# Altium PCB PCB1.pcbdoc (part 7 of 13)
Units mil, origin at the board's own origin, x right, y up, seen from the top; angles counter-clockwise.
Board outline 5895.51 x 5895.51 mil, 8 copper layers (Top Layer, L2_GND1, L3_SIG1, L4_GND2, L5_PWR, L6_SIG2, L7_GND3, Bottom Layer), stack 63.761 mil thick; 673 components, 558 nets, 2797 pads, 1861 vias.
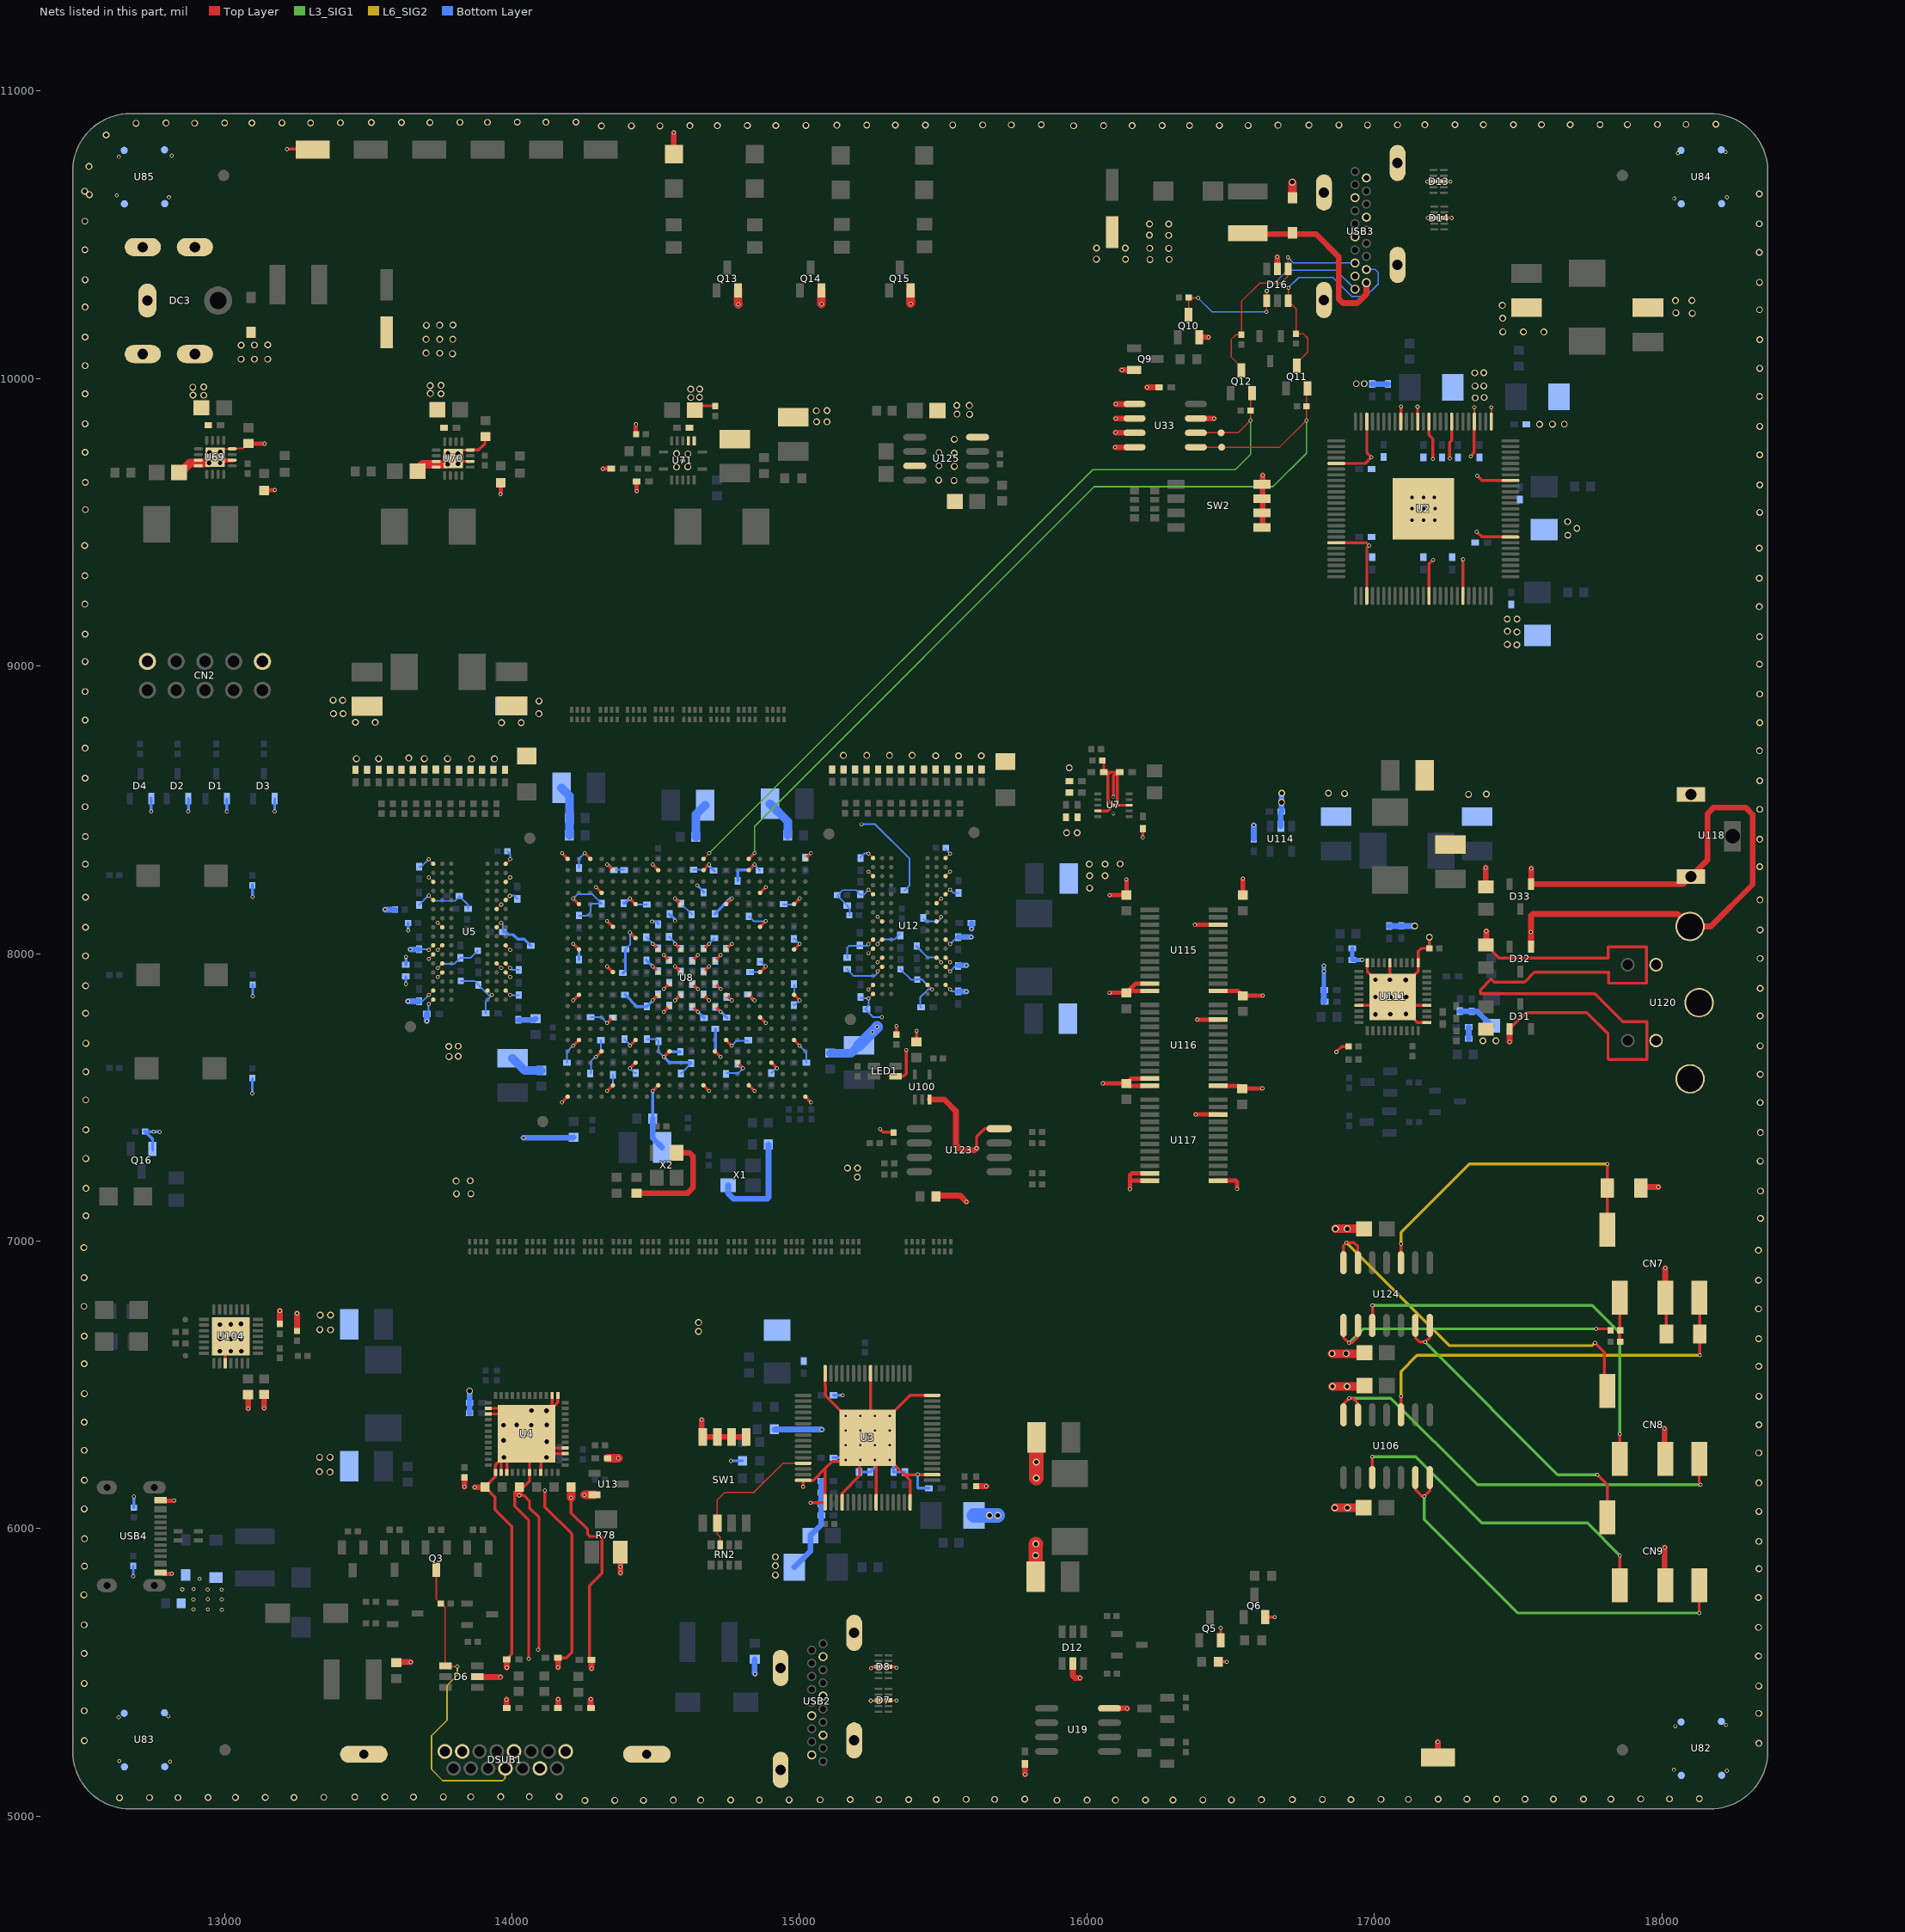
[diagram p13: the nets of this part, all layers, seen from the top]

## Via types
v1: diameter 23.62, hole 15.75, Top Layer to Bottom Layer, 621 vias
v2: diameter 13.8, hole 7.9, Top Layer to Bottom Layer, 567 vias
v3: diameter 13.78, hole 7.87, Top Layer to Bottom Layer, 529 vias
v4: diameter 13.78, hole 7.9, Top Layer to Bottom Layer, 114 vias
v5: diameter 15.75, hole 7.87, Top Layer to Bottom Layer, 16 vias
v6: diameter 24, hole 12, Top Layer to Bottom Layer, 10 vias
v7: diameter 11.81, hole 7.87, Top Layer to Bottom Layer, 4 vias

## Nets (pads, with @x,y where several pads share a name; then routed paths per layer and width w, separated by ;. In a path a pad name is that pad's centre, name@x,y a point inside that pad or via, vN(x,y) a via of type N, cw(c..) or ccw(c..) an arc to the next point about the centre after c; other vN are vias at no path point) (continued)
GND: C1.1 C2.1 C3.1 C4.1 C5.1 C6.1 C7.1 C8.1 C9.1 C10.1 C11.1 C12.1 C13.1 C14.1 C15.1 C16.1 C17.1 C18.1 C19.1 C20.1 C21.1 C22.1 C23.1 C24.1 C25.1 C29.1 C30.1 C31.1 C32.1 C33.1 C34.1 C35.1 C36.1 C37.1 C38.1 C39.1 C40.1 C41.1 C42.1 C43.1 C44.1 C45.1 C46.1 C47.1 C48.1 C49.1 C50.1 C51.1 C52.1 C53.1 C54.1 C55.1 C56.1 C57.1 C58.1 C59.1 C60.1 C61.1 C62.1 C63.1 C64.1 C65.1 C66.1 C67.1 C68.1 C69.1 C70.1 C71.1 C72.1 C73.1 C74.1 C75.1 C76.1 C77.1 C78.1 C79.1 C80.1 C81.1 C82.1 C83.1 C84.1 C85.1 C86.1 C87.1 C88.1 C89.1 C90.1 C91.1 C92.1 C93.1 C94.1 C95.1 C96.1 C97.1 C98.1 C99.1 C100.1 C101.1 C102.2 C103.2 C104.2 C105.2 C106.2 C107.1 C108.2 C109.1 C111.1 C112.1 C113.1 C114.1 C115.1 C116.1 C117.1 C118.1 C119.2 C120.1 C121.1 C122.1 C123.1 C124.2 C125.1 C128.1 C129.2 C132.2 C133.2 C135.2 C136.2 C141.1 C142.1 C143.1 C144.1 C145.1 C146.1 C147.1 C148.1 C149.1 C150.1 C153.2 C157.2 C158.2 C159.2 C162.2 C166.1 C167.1 C169.1 C171.1 C173.2 C176.1 C178.2 C179.2 C180.2 C181.2 C182.2 C183.2 C184.2 C185.1 C186.1 C187.1 C188.1 C189.1 C190.1 C191.1 C192.2 C193.1 C194.1 C195.1 C196.1 C197.1 C198.1 C199.1 C200.1 C201.1 C204.1 C205.1 C206.1 C207.1 C208.1 C209.1 C210.1 C211.1 C212.1 C213.1 C214.1 C215.1 C216.1 C217.2 C218.2 C219.2 C220.1 C221.1 C222.1 C223.1 C224.1 C225.1 C226.1 C227.1 C228.1 C229.1 C230.1 C231.1 C232.1 C233.1 C234.1 C235.1 C236.1 C237.1 C238.1 C239.1 C240.1 C241.1 C242.1 C243.1 C244.1 C245.1 C246.1 C247.1 C248.1 C249.1 C250.1 C251.1 C259.2 C260.2 C261.1 C262.1 C263.1 C264.1 C265.1 C266.1 C267.1 C268.1 C269.1 C270.1 C271.1 C272.1 C273.1 C274.1 C275.1 C276.1 C277.1 C278.1 C279.1 C280.1 C281.1 C282.1 C283.1 C284.1 C285.1 C286.1 C287.1 C288.1 C289.1 C290.1 C291.1 C292.1 C293.1 C294.1 C295.1 C296.1 C297.1 C298.1 C299.1 C300.1 C301.1 C302.1 C303.1 C304.1 C305.1 C306.1 C307.1 C308.1 C309.1 C310.1 C311.1 C312.1 C313.1 C314.1 C315.1 C319.2 C322.2 C328.1 C329.1 C330.1 C331.2 C332.1 C333.2 C334.1 C335.2 C336.1 C337.1 C338.1 C339.2 C340.1 C343.1 C344.1 C345.2 C346.2 C347.2 C348.2 C349.2 C350.2 C351.1 C352.1 C354.1 C355.1 C356.1 C357.1 CN2.2 CN2.10 CN7.3 CN8.3 CN9.3 D1.1 D2.1 D3.1 D4.1 D6.2 D7.3 D7.8 D8.3 D8.8 D12.2 D13.3 D13.8 D14.3 D14.8 D16.2 D20.2 D21.2 D26.2 D30.2 D31.1 D32.1 D33.1 DC3.4 DC3.6 DSUB1.5 DSUB1.6 DSUB1.7 DSUB1.8 DSUB1.10 DSUB1.16 DSUB1.17 L36.2 LED1.2 Q5.2 Q6.2 Q9.2 Q10.2 Q13.2 Q14.2 Q15.2 Q16.2 R1.2 R2.2 R25.1 R26.2 R51.2 R52.2 R53.2 R78.3 R84.1 R85.1 R86.1 R97.1 R103.1 R120.2 R121.2 R134.1 R137.1 R139.1 R141.1 R149.1 R158.1 R170.2 R172.2 R174.2 R175.1 R176.1 R185.1 R186.2 R187.2 R188.2 R189.2 R193.2 R194.1 R196.1 R197.1 R198.1 SW1.5 SW1.6 SW1.7 SW1.8 SW2.5 SW2.6 SW2.7 SW2.8 U2.5 U2.19 U2.28 U2.39 U2.45 U2.58 U2.68 U2.76 U2.79 U2.83 U2.87 U2.89 U2.92 U2.98 U2.101 U3.16 U3.17 U3.20 U3.26 U3.32 U3.34 U3.48 U3.56 U3.64 U3.65 U4.1 U4.2 U4.14 U4.15 U4.25 U4.26 U4.27 U4.31 U4.33 U4.39 U4.40 U4.49 U5.A9 U5.B1 U5.B3 U5.B9 U5.D1 U5.D8 U5.E1 U5.E2 U5.E8 U5.F9 U5.G1 U5.G8 U5.G9 U5.J2 U5.J8 U5.L2 U5.M1 U5.M9 U5.P1 U5.P9 U5.T1 U5.T9 U7.4 U7.8 U7.11 U8.A1 U8.A3 U8.A22 U8.AA5 U8.AA9 U8.AA13 U8.AA17 U8.AB1 U8.AB22 U8.B5 U8.B9 U8.B13 U8.B17 U8.D4 U8.D18 U8.E2 U8.E7 U8.E11 U8.E15 U8.E21 U8.G5 U8.G18 U8.H7 U8.J2 U8.J9 U8.J11 U8.J13 U8.J15 U8.J21 U8.K10 U8.K12 U8.K14 U8.L5 U8.L9 U8.L11 U8.L13 U8.L18 U8.M10 U8.M12 U8.M14 U8.N2 U8.N9 U8.N11 U8.N13 U8.N15 U8.N17 U8.N21 U8.P10 U8.P12 U8.P14 U8.R5 U8.R18 U8.U2 U8.U7 U8.U15 U8.U21 U8.V4 U8.V10 U8.V14 U8.W7 U8.W16 U8.W19 U12.A9 U12.B1 U12.B3 U12.B9 U12.D1 U12.D8 U12.E1 U12.E2 U12.E8 U12.F9 U12.G1 U12.G8 U12.G9 U12.J2 U12.J8 U12.L2 U12.M1 U12.M9 U12.P1 U12.P9 U12.T1 U12.T9 U13.2 U14.1 U19.4 U25.1 U33.1 U33.2 U33.3 U33.4 U33.7 U69.6 U69.8 U69.15 U69.16 U69.17 U70.6 U70.8 U70.15 U70.16 U70.17 U71.2 U71.3 U71.15 U75.1 U76.1 U77.1 U82.1 U82.2 U82.3 U82.4 U83.1 U83.2 U83.3 U83.4 U84.1 U84.2 U84.3 U84.4 U85.1 U85.2 U85.3 U85.4 U100.3 U102.1 U104.3 U104.29 U105.2 U111.7 U111.21 U111.24 U111.31 U111.36 U111.40 U111.41 U114.2 U115.11 U115.12 U115.13 U115.22 U116.11 U116.12 U116.13 U116.22 U117.11 U117.12 U117.13 U117.22 U118.2 U118.3 U120.1 U120.2 U120.5 U120.6 U120.7 U122.1 U123.4 U125.3 U125.8 USB2.2 USB2.5 USB2.8 USB2.11 USB2.17 USB2.20 USB3.2 USB3.5 USB3.8 USB3.11 USB3.17 USB3.20 USB4.1 USB4.12 X1.2 X2.2 | length 35669.5
  Top Layer w4.7: v2(13710.63,7824.03) U5.A9@13726.38,7839.78 ; v2(13710.63,7855.53) U5.B9@13726.38,7871.28 ; v2(13710.63,7981.52) U5.F9@13726.38,7997.26 ; v2(13710.63,8013.02) U5.G9@13726.38,8028.76 ; v2(13710.63,8201.99) U5.M9@13726.38,8186.24 ; v2(13710.63,8264.98) U5.P9@13726.38,8249.23 ; v2(13710.63,8327.97) U5.T9@13726.38,8312.22 ; v2(13742.12,7918.52) U5.D8@13757.87,7934.27 ; v2(13742.12,7950.02) U5.E8@13757.87,7965.76 ; v2(13742.12,8013.02) U5.G8@13757.87,8028.76 ; v2(13742.12,8107.49) U5.J8@13757.87,8091.75 ; U5.B3@13915.35,7871.28 v2(13931.09,7855.53) ; U5.E2@13946.85,7965.76 v2(13962.59,7950.02) ; U5.J2@13946.85,8091.75 v2(13962.59,8107.49) ; U5.L2@13946.85,8154.74 v2(13962.59,8170.48) ; U5.B1@13978.34,7871.28 v2(13994.08,7855.53) ; U5.D1@13978.34,7934.27 v2(13994.08,7918.52) ; U5.E1@13978.34,7965.76 v2(13994.08,7950.02) ; U5.G1@13978.34,8028.76 v2(13994.08,8013.02) ; U5.M1@13978.34,8186.24 13978.34,8186.46 v2(13992.51,8200.62) ; U5.P1@13978.34,8249.23 v2(13994.08,8264.98) ; U5.T1@13978.34,8312.22 v2(13994.08,8327.97) ; v2(15240.63,7844.03) U12.A9@15256.38,7859.78 ; v2(15240.63,7875.53) U12.B9@15256.38,7891.28 ; v2(15240.63,8001.52) U12.F9@15256.38,8017.26 ; v2(15240.63,8033.02) U12.G9@15256.38,8048.76 ; v2(15240.63,8221.99) U12.M9@15256.38,8206.24 ; v2(15240.63,8284.98) U12.P9@15256.38,8269.23 ; v2(15240.63,8347.97) U12.T9@15256.38,8332.22 ; v3(15248.36,5402) 15273.76,5402 D7.8@15274.92,5403.16 ; v2(15272.12,7938.52) U12.D8@15287.87,7954.27 ; v2(15272.12,7970.02) U12.E8@15287.87,7985.76 ; v2(15272.12,8033.02) U12.G8@15287.87,8048.76 ; v2(15272.12,8127.49) U12.J8@15287.87,8111.75 ; D7.3@15309.58,5403.16 v3(15337.36,5403.16) ; U12.B3@15445.35,7891.28 v2(15461.09,7875.53) ; U12.E2@15476.85,7985.76 v2(15492.59,7970.02) ; U12.J2@15476.85,8111.75 v2(15492.59,8127.49) ; U12.L2@15476.85,8174.74 v2(15492.59,8190.48) ; U12.B1@15508.34,7891.28 v2(15524.08,7875.53) ; U12.D1@15508.34,7954.27 v2(15524.08,7938.52) ; U12.E1@15508.34,7985.76 v2(15524.08,7970.02) ; U12.G1@15508.34,8048.76 v2(15524.08,8033.02) ; U12.M1@15508.34,8206.24 v2(15524.08,8221.99) ; U12.P1@15508.34,8269.23 v2(15524.08,8284.98) ; U12.T1@15508.34,8332.22 v2(15524.08,8347.97)
  Top Layer w5: U69.17@12979.36,9752.17 12982.08,9754.89 U69.8@13027.74,9754.89 ; U69.8@13029.69,9757.02 13066.99,9757.02 C195.1@13085.26,9775.29
  Top Layer w6.2: U2.79@17347.52,9850.15 v3(17347.52,9900) ; v3(17406.36,9900) 17406.58,9899.78 U2.76@17406.58,9850.15
  Top Layer w10: U104.3@13003.01,6575.31 13003.01,6649.23 U104.29@13022.69,6668.91 ; v3(13217.85,10797.25) 13218.27,10797.67 U75.1@13307.73,10797.67 ; U70.17@13791.43,9711.95 13854.5,9711.95 U70.6@13855.13,9711.32 ; U70.17@13807.82,9730.95 13827.83,9750.97 U70.8@13855.03,9750.97 ; U70.8@13859.91,9751.64 13884.78,9751.64 13905.96,9772.82 13905.96,9800.41 C198.1@13908.29,9802.74 ; U4.15@13917.5,6398.9 U4.49@13982.46,6398.9 ; U4.14@13917.5,6418.58 13962.78,6418.58 U4.49@13982.46,6398.9 ; U4.26@13962.78,6196.14 U4.49@13962.78,6241.42 ; C114.1@13981.9,5546 13999.36,5563.46 13999.36,6008 13941.36,6066 13941.36,6110.34 13907.69,6144.01 R84.1@13906.7,6145 13943.09,6181.39 U4.25@13943.09,6196.14 13943.09,6221.73 U4.49@13962.78,6241.42 ; U4.27@13982.46,6196.14 U4.49@13982.46,6261.1 ; v4(14025.49,6116.04) 14042.32,6116.04 14061.36,6097 14061.36,6072 14094.36,6039 14094.36,5582 v3(14091.36,5579) ; R85.1@14025.49,6143.79 14009.36,6127.66 14009.36,6079 14058.36,6030 v4(14058.36,5548) ; R85.1@14026.7,6145 14041.36,6145 14061.2,6164.84 U4.31@14061.2,6196.14 U4.49@14061.2,6320.16 ; U4.33@14100.57,6196.14 U4.49@14100.57,6280.79 ; v3(14114.36,6133) 14114.36,6076 14208.36,5982 14208.36,5570 14189.36,5551 C113.1@14159.82,5551 ; U4.2@14139.94,6463.86 U4.49@14139.94,6418.58 ; U4.1@14159.63,6463.86 14159.63,6438.27 U4.49@14139.94,6418.58 ; v2(14174.29,7482.92) U8.AB1@14193.96,7502.6 ; v2(14174.29,8349.07) U8.A1@14193.96,8329.4 ; U4.39@14185.22,6261.1 14120.26,6261.1 U4.49@14100.57,6280.79 ; U4.40@14185.22,6280.79 U4.49@14100.57,6280.79 ; v3(14206.02,6108) 14206.02,6054.34 14263.36,5997 14263.36,5981 14271.36,5973 14313.36,5973 14313.36,5845 14270.36,5802 14270.36,5550.46 C112.1@14277.13,5543.68 ; v2(14213.67,7679.79) U8.U2@14233.34,7699.47 ; v2(14213.67,7837.27) U8.N2@14233.34,7856.94 ; v2(14213.67,8034.1) U8.J2@14233.34,8014.43 ; v2(14213.67,8191.57) U8.E2@14233.34,8171.9 ; v2(14253.04,8349.07) U8.A3@14272.71,8329.4 ; v2(14292.41,7640.42) U8.V4@14312.08,7660.1 ; v2(14292.41,8230.95) U8.D4@14312.08,8211.27 ; v2(14331.79,7522.32) U8.AA5@14351.46,7542 ; v2(14331.79,7758.52) U8.R5@14351.46,7778.2 ; v2(14331.79,7955.37) U8.L5@14351.46,7935.7 ; v2(14331.79,8112.84) U8.G5@14351.46,8093.16 ; v2(14331.79,8309.69) U8.B5@14351.46,8290.01 ; v2(14410.52,7601.05) U8.W7@14430.19,7620.73 ; v2(14410.52,7679.79) U8.U7@14430.19,7699.47 ; v2(14410.52,8073.47) U8.H7@14430.19,8053.8 ; v2(14410.52,8191.57) U8.E7@14430.19,8171.9 ; v2(14489.26,7522.32) U8.AA9@14508.93,7542 ; v2(14489.26,7837.27) U8.N9@14508.93,7856.94 ; v2(14489.26,7955.37) U8.L9@14508.93,7935.7 ; v2(14489.26,8034.1) U8.J9@14508.93,8014.43 ; v2(14489.26,8309.69) U8.B9@14508.93,8290.01 ; v2(14528.63,7640.42) U8.V10@14548.3,7660.1 ; v2(14528.63,7797.9) U8.P10@14548.3,7817.57 ; v2(14528.63,7876.62) U8.M10@14548.3,7896.3 ; v2(14528.63,7994.73) U8.K10@14548.3,7975.06 ; v2(14567.99,7837.27) U8.N11@14587.66,7856.94 ; v2(14567.99,7955.37) U8.L11@14587.66,7935.7 ; v2(14567.99,8034.1) U8.J11@14587.66,8014.43 ; v2(14567.99,8191.57) U8.E11@14587.66,8171.9 ; U8.P12@14627.06,7817.57 v2(14646.74,7797.9) ; U8.M12@14627.06,7896.3 v2(14646.74,7876.62) ; U8.K12@14627.06,7975.06 v2(14646.74,7994.73) ; C199.1@14651.76,9901.92 14654.81,9904.97 R139.1@14703.55,9904.97 ; U8.AA13@14666.41,7542 v2(14686.09,7522.32) ; U8.N13@14666.41,7856.94 v2(14686.09,7837.27) ; U8.L13@14666.41,7935.7 v2(14686.09,7955.37) ; U8.J13@14666.41,8014.43 v2(14686.09,8034.1) ; U8.B13@14666.41,8290.01 v2(14686.09,8309.69) ; U8.V14@14705.78,7660.1 v2(14725.46,7640.42) ; U8.P14@14705.78,7817.57 v2(14725.46,7797.9) ; U8.M14@14705.78,7896.3 v2(14725.46,7876.62) ; U8.K14@14705.78,7975.06 v2(14725.46,7994.73) ; U8.U15@14745.16,7699.47 v2(14764.84,7679.79) ; U8.N15@14745.16,7856.94 v2(14764.84,7837.27) ; U8.J15@14745.16,8014.43 v2(14764.84,8034.1) ; U8.E15@14745.16,8171.9 v2(14764.84,8191.57) ; U8.W16@14784.52,7620.73 v2(14804.2,7601.05) ; U8.AA17@14823.89,7542 v2(14843.57,7522.32) ; U8.N17@14823.89,7856.94 v2(14843.57,7837.27) ; U8.B17@14823.89,8290.01 v2(14843.57,8309.69) ; U8.R18@14863.26,7778.2 v2(14882.94,7758.52) ; U8.L18@14863.26,7935.7 v2(14882.94,7955.37) ; U8.G18@14863.26,8093.16 v2(14882.94,8112.84) ; U8.D18@14863.26,8211.27 v2(14882.94,8230.95) ; U8.W19@14902.63,7620.73 v2(14922.31,7601.05) ; U8.U21@14981.36,7699.47 v2(15001.04,7679.79) ; U8.N21@14981.36,7856.94 v2(15001.04,7837.27) ; U8.J21@14981.36,8014.43 v2(15001.04,8034.1) ; U8.E21@14981.36,8171.9 v2(15001.04,8191.57) ; v3(15012.95,6146) U3.16@15012.95,6168.36 15048.72,6168.36 15089.72,6209.36 ; U8.AB22@15020.76,7502.6 v2(15040.44,7482.92) ; U8.A22@15020.76,8329.4 v2(15040.44,8349.07) ; v3(15038.36,6090) 15088.13,6090 U3.17@15089.72,6091.59 15089.72,6209.36 ; U3.64@15089.72,6540.41 15089.72,6499.64 15090.36,6499 15090.36,6463 v5(15160.59,6392.77) v5(15211.77,6341.59) U3.65@15237.36,6316 ; U3.20@15148.78,6091.59 15148.78,6123.42 15209.36,6184 U3.65@15209.36,6288 ; U3.56@15247.2,6540.41 15247.2,6325.84 U3.65@15237.36,6316 ; v3(15249.36,5515) 15254.35,5519.99 D8.8@15274.77,5519.99 D8.3@15309.43,5519.99 15333.37,5519.99 v3(15337.36,5516) ; U3.26@15266.89,6091.59 U3.65@15266.89,6286.47 ; D7.8@15274.92,5403.16 D7.3@15309.58,5403.16 ; v3(15280.67,7389.79) 15291.71,7378.76 R25.1@15327.06,7378.76 ; v5(15314.13,6392.77) 15385,6463.64 U3.48@15461.77,6463.64 ; LED1.2@15334.76,7573.28 15361.64,7573.28 15371.36,7583 v3(15371.36,7665) ; R185.1@15337.36,7718.04 v3(15337.36,7748) ; U3.32@15385,6091.59 15385,6168.36 15365.31,6188.05 ; C1.1@15407.36,7693.56 v3(15407.36,7732) ; v3(15411.36,6189) 15410.98,6188.62 v3@15410.98,6188.05 ; U3.34@15461.77,6188.05 v3@15410.98,6188.05 ; v3(15616.36,7323) 15616.36,7364 15643.61,7391.26 U123.4@15695.16,7391.26 ; U7.4@16037.24,8496.3 16072.65,8496.3 U7.11@16092.35,8516 ; R97.1@16053.4,8671 16058.82,8665.58 C119.2@16058.82,8631 16081.8,8631 ; v7(16092.35,8545.53) 16092.35,8619 C125.1@16104.35,8631 ; U7.8@16147.47,8516 v7(16106.13,8516) ; v3(16194.36,8404) C124.2@16194.36,8434.54 ; U25.1@16457.64,5536.71 v3(16486.36,5536.71) ; Q5.2@16465.38,5612.34 v3(16465.38,5655) ; Q6.2@16620.38,5692.34 v3(16653.36,5692.34) ; U2.19@16867.21,9428.89 16971.47,9428.89 v3(16981.36,9419) 16973.51,9411.15 U2.28@16973.51,9243.85 ; U2.5@16867.21,9704.48 16967.84,9704.48 v3(16989.36,9726) 16973.51,9741.85 U2.98@16973.51,9850.15 ; v3(16867.36,7658) 16886.14,7676.79 R172.2@16910,7676.79 ; U111.7@16945.55,7819.74 17034.13,7819.74 U111.41@17063.66,7849.27 ; U111.40@16975.08,7967.38 16975.08,7937.85 v1(17003.59,7909.33) U111.41@17053.82,7859.11 ; U111.36@17053.82,7967.38 v1(17053.82,7909.02) U111.41@17053.82,7859.11 ; U2.92@17092.12,9851.39 17092.12,9901.94 v3(17092.21,9902.04) ; U2.89@17149.99,9872.57 v3(17149.99,9901.94) ; U111.21@17181.77,7760.69 17149.67,7760.69 17063.66,7846.7 U111.41@17063.66,7849.27 ; U111.24@17181.77,7819.74 17093.19,7819.74 U111.41@17063.66,7849.27 ; v3(17183.36,10684.99) D13.3@17206.03,10684.99 ; v3(17185.36,10557.99) D14.3@17208.03,10557.99 ; U2.87@17189.18,9872.58 17189.18,9804.4 17203.13,9790.45 v3(17203.13,9720.71) ; U2.39@17190.04,9243.85 17190.04,9354.68 v3(17204.36,9369) ; v1(17191.32,8057) R170.2@17191.32,8018 17162.36,8018 17152.24,8007.88 U111.31@17152.24,7967.38 17152.24,7937.85 U111.41@17063.66,7849.27 ; D13.8@17240.69,10684.99 v3(17264.36,10684.99) ; D14.8@17242.69,10557.99 v3(17268.36,10557.99) ; v3(17262.3,9721.38) 17261.63,9722.04 17261.63,9776.95 17268.72,9784.03 U2.83@17268.72,9867.71 ; U2.45@17308.15,9243.85 17308.15,9370.79 v3(17308.36,9371) ; v3(17334.19,9729.68) 17347.03,9742.52 U2.79@17347.03,9848.34 ; v3(17355.72,9466.73) 17373.21,9449.24 U2.58@17473.94,9449.24 ; v3(17357.77,9661.55) 17373.71,9645.61 U2.68@17474.88,9645.61 ; R175.1@17387.36,8030.37 17432.73,7985 17813.36,7985 17813.36,8023 17946.36,8023 17946.36,7897 17814.36,7897 17814.36,7935 17556.36,7935 17522.36,7901 17416.36,7901 17406.36,7911 17405.36,7911 17368.36,7874 17369.36,7873 17369.36,7860 17766.36,7860 17863.36,7763 17947.36,7763 17947.36,7631 17946.36,7632 17814.36,7632 17812.36,7634 17812.36,7721 17738.36,7795 17527.32,7795 D31.1@17469.96,7737.64 ; CN7.3@18011.34,6803.66 18015.14,6799.86 R194.1@18015.14,6677 ; U4.49@13962.78,6241.42 U4.49@13982.46,6261.1 ; U4.49@13982.46,6261.1 U4.49@14051.36,6330 ; U4.49@13982.46,6398.9 U4.49@14051.36,6330 ; U4.49@14051.36,6330 U4.49@14061.2,6320.16 ; U4.49@14051.36,6330 U4.49@14139.94,6418.58 ; U4.49@14061.2,6320.16 U4.49@14100.57,6280.79 ; 15089.72,6209.36 15114.36,6234 15155.36,6234 U3.65@15209.36,6288 ; U3.65@15209.36,6288 v5(15211.77,6290.41) U3.65@15237.36,6316 ; U3.65@15237.36,6316 v5(15262.95,6290.41) U3.65@15266.89,6286.47 ; U3.65@15266.89,6286.47 v5(15314.13,6239.23) 15365.31,6188.05 ; 15365.31,6188.05 v3@15410.98,6188.05 ; 16081.8,8631 16074.8,8624 16073.36,8624 16073.36,8535 U7.11@16092.35,8516 ; 16081.8,8631 C125.1@16104.35,8631 ; U7.11@16092.35,8516 v7(16106.13,8516) ; C125.1@16104.35,8631 C125.1@16113.9,8631 16106.13,8623.24 v7(16106.13,8516) ; U111.41@17053.82,7859.11 U111.41@17063.66,7849.27
  Top Layer w15: USB4.1@12778.61,6097.53 v3(12825.25,6097.53) ; USB4.12@12786.34,5843.61 12817.17,5843.61 v3(12817.32,5843.45) ; U69.17@12965.45,9715.85 12965.74,9715.56 U69.6@13027.82,9715.56 ; C195.1@13085.26,9775.29 13087.4,9773.15 v3(13140.05,9773.15) ; R134.1@13140.22,9612.13 13175.49,9612.13 v3(13175.59,9612.23) ; R137.1@13960.14,9636.33 13960.99,9635.49 v4@13960.99,9598.13 ; v3(14316.34,9685.63) 14316.63,9685.93 C201.1@14342.28,9685.93 ; R141.1@14430.88,9806.59 14430.88,9840.4 v3(14431.17,9840.7) ; v3(14434.09,9607.52) C200.1@14434.09,9640.17 ; v3(16055.36,7548.56) C347.2@16137.36,7548.56 ; v3(16078.36,7864) 16078.8,7863.56 C349.2@16137.36,7863.56 C349.2@16144.06,7870.26 ; v3(16079.36,8203) 16136.8,8203 C345.2@16137.36,8203.56 v4(16137.36,8258) ; v3(16149.36,7181) 16149.36,7211.37 ; U117.12@16218.36,7210.26 16150.47,7210.26 16149.36,7211.37 ; U117.11@16218.36,7235.84 16155.2,7235.84 16149.36,7230 16149.36,7211.37 ; U116.12@16218.36,7540.26 16145.66,7540.26 C347.2@16137.36,7548.56 ; U116.11@16218.36,7565.84 16154.64,7565.84 C347.2@16137.36,7548.56 ; U115.12@16218.36,7870.26 C349.2@16144.06,7870.26 ; U115.11@16218.36,7895.84 16169.64,7895.84 C349.2@16144.06,7870.26 ; v3(16375.36,8100.56) U115.22@16456.36,8100.56 ; v3(16377.36,7440.56) U117.22@16456.36,7440.56 ; v3(16383.36,7771) 16383.8,7770.56 U116.22@16456.36,7770.56 ; U117.13@16456.36,7210.26 16517.1,7210.26 16522.36,7205 v3(16522.36,7182) ; U116.13@16456.36,7540.26 16530.66,7540.26 C348.2@16540.36,7530.56 16609.92,7530.56 v3(16610.36,7531) ; U115.13@16456.36,7870.26 16525.66,7870.26 C350.2@16542.36,7853.56 16610.92,7853.56 v3(16611.36,7854) ; C346.2@16542.36,8203.56 v4(16542.36,8261)
  Top Layer w20: v3(13082.69,6418) C314.1@13082.69,6466.35 ; v3(13138.36,6419) C315.1@13138.36,6466.44 ; U105.2@13192.69,6712.6 v3(13192.69,6758) ; R158.1@13252.69,6687.6 v3(13252.69,6749) ; C118.1@13592.38,5536.25 13648.15,5536.25 v3(13648.29,5536.1) ; v3(13834.55,6145.38) 13834.78,6145.6 U14.1@13834.78,6178.18 ; v3(13870.77,6144.01) R84.1@13907.69,6144.01 ; D6.2@13882.31,5484.12 13960.47,5484.12 v3(13960.67,5484.32) ; C115.1@13978.16,5376.48 13981.07,5379.39 v3(13981.07,5406.2) ; v3(13982.24,5516.96) C114.1@13982.24,5544.36 ; C116.1@14160.65,5375.81 v3(14160.62,5407.29) ; C113.1@14160.91,5550.92 14160.91,5517.69 v3(14161.2,5517.4) ; C117.1@14274,5376.1 14274,5405.83 v3(14274.87,5406.71) ; C112.1@14276.91,5543.11 14276.91,5514.26 v3(14277.2,5513.97) ; v4@14377.61,5845.72 14377.61,5921.65 R78.3@14378.66,5922.7 ; C148.1@14433.7,7166.48 14610.36,7166.48 14630.36,7186.48 14630.36,7295 14618,7307.35 X2.2@14573.15,7307.35 ; U77.1@14563.18,10780.41 v3(14563.18,10855) ; SW1.8@14659.1,6318.72 14817.8,6318.72 SW1.5@14818.46,6319.37 ; SW1.8@14660.63,6325.27 v3(14660.63,6379.05) ; U100.3@15452.95,7492.69 15503.66,7492.69 15544.36,7452 15544.36,7335 15563.36,7316 15609.36,7316 v3(15616.36,7323) ; C2.1@15472.87,7158.33 15559.43,7158.33 v3(15580.85,7136.91) ; R103.1@15614.36,6147.96 v3(15650.36,6147.96) ; C150.1@15784.32,5182.92 15784.32,5146.36 v3(15785.01,5145.67) ; D12.2@15950.92,5531.21 15950.92,5488.44 15958.36,5481 v3(15975.36,5481) ; U19.4@16078.46,5375.41 16139.95,5375.41 v4(16140.36,5375) ; v3(16098.36,9761) U33.4@16165.86,9761 ; v3(16099.36,9812) 16100.36,9811 U33.3@16165.86,9811 ; v3(16100.36,9861) U33.2@16165.86,9861 ; v3(16100.36,9911) U33.1@16165.86,9911 ; v3(16121.36,10030) Q9.2@16163.89,10029.96 ; v3(16209.36,9969) C210.1@16250.9,9969 ; U33.7@16378.86,9861 v3(16442.36,9861) ; Q10.2@16390.66,10142.99 v3(16422.36,10142.99) ; SW2.5@16611.53,9482.97 v4@16611.53,9663.29 ; D16.2@16662.36,10381.12 v3(16662.36,10423) ; U76.1@17220.15,5205.03 v3(17220.15,5258.33) ; R175.1@17387.36,8030.37 17389.36,8032.37 v3(17389.36,8078) ; R174.2@17387.36,8232.37 v3(17387.36,8299) ; v3(17469.96,7693) D31.1@17469.96,7737.64 ; v3(17544.36,8075) v3@17544.76,8074.6 ; D32.1@17544.76,8024.36 v3@17544.76,8074.6 ; D33.1@17544.76,8241.36 D33.1@17545.36,8241.96 ; v3(17545.36,8296) D33.1@17545.36,8241.96 ; R193.2@17926.52,7188.49 v3@17987.21,7188.49 ; v3(18008.74,6348.18) 18009.18,6347.74 CN8.3@18009.18,6243.68 ; CN9.3@18009.25,5805.32 18009.25,5935.02 v3(18009.54,5935.31) ; CN7.3@18011.34,6803.66 v3@18011.34,6907 ; v3@17544.76,8074.6 17544.76,8132.4 17550.36,8138 18054,8138 U120.7@18097.59,8094.41 18169.77,8094.41 18315.36,8240 18315.36,8483 18290.36,8508 18180.36,8508 18158.36,8486 18158.36,8325 18157.34,8325 U118.3@18100.44,8268.1 18074.3,8241.96 D33.1@17545.36,8241.96
  Top Layer w25: v4@14025.49,6120.14 14025.49,6143.79 R85.1@14026.7,6145
  Top Layer w30: C194.1@12843.93,9669.27 12881.05,9706.38 U69.17@12943.22,9706.38 ; C197.1@13666.07,9678.28 13689.97,9702.18 U70.17@13774.5,9702.18 ; v3(14206.02,6108) R86.1@14206.02,6145 ; v3(14252.36,6117.6) U13.2@14287.73,6117.6 ; C111.1@14332.82,6245 v3(14370.36,6245) ; Q13.2@14786.76,10306.63 14786.76,10258.6 v3(14787.36,10258) ; v3(15076.76,10259) Q14.2@15076.76,10306.63 ; Q15.2@15386.76,10306.63 15386.76,10260.6 v3(15387.36,10260) ; D21.2@16713.75,10629.22 16714.75,10630.21 v1@16714.75,10681.02 ; v1(16852.36,6609) v1(16901.47,6609) 16961.99,6609 C357.1@16964.99,6612 ; v1(16854.36,6495) v1(16904.68,6495) 16961.99,6495 C354.1@16964.99,6498 ; v1(16862.36,6073) v1(16905.81,6073) C355.1@16962.99,6073 ; v1(16864.36,7043) v1(16905.32,7043) C356.1@16963.99,7043
  Top Layer w50: C212.1@15821.91,5833 v1(15821.91,5907.36) 15821.91,5946.56 v1(15822.36,5947) ; v1(15824.2,6176) v1(15824.2,6231.74) C211.1@15824.2,6317.79
  Bottom Layer w4: v2(13710.63,8201.99) 13729.73,8182.89 13802.24,8182.89 13816.96,8197.61 C102.2@13816.96,8200.03 ; R53.2@15132.1,8201.73 15151.01,8220.63 15196.3,8220.63 15212.15,8204.78 15223.43,8204.78 v2(15240.63,8221.99)
  Bottom Layer w4.7: R52.2@15507.44,8365.27 15507.44,8364.61 v2(15524.08,8347.97)
  Bottom Layer w6: C274.1@13677.36,7834.54 13689.64,7834.54 v2(13710.63,7855.53) ; C266.1@13677.36,8014.54 13709.11,8014.54 v2(13710.63,8013.02) ; C267.1@13677.36,8169.54 13709.8,8201.99 v2(13710.63,8201.99) ; C268.1@13677.36,8302.46 13685.13,8302.46 v2(13710.63,8327.97) ; C273.1@13703.9,7790 13710.63,7796.73 v2(13710.63,7824.03) ; v2(13742.12,7950.02) 13757.11,7965 13800.1,7965 C269.1@13820.98,7985.88 13857.2,7985.88 R189.2@13881.36,8010.04 ; C102.2@13816.96,8200.03 13847.56,8169.43 C276.1@13847.56,8156.16 ; R188.2@13822.36,7904.96 13869.73,7904.96 C272.1@13883.14,7891.55 13919.16,7855.53 v2(13931.09,7855.53) 13909.34,7833.78 C263.1@13909.34,7792.35 ; v2(13962.59,8107.49) 13968.97,8101.12 C264.1@13968.97,8075.32 ; R2.2@13984.4,8356 13994.08,8346.32 v2(13994.08,8327.97) ; v2(13992.51,8200.62) 13993.87,8201.99 14007.91,8201.99 C261.1@14019.36,8190.54 ; v2(13994.08,7855.53) 14023.2,7855.53 C262.1@14023.62,7855.95 ; v2(13994.08,7950.02) 14001.1,7943 C270.1@14024.57,7943 ; C52.1@14191.77,7620.88 14191.77,7659.42 14212.15,7679.79 v2(14213.67,7679.79) ; v2(14213.67,8191.57) 14228.1,8206 14279.82,8206 C46.1@14311.82,8174 ; C51.1@14233.36,8132.46 14261.82,8132.46 14274.36,8145 14274.36,8170 14278.36,8174 C46.1@14311.82,8174 ; C48.1@14233.36,8297.46 14233.36,8329.39 v2(14253.04,8349.07) ; C56.1@14272.62,7583.42 14275.36,7586.16 14275.36,7627 14288.78,7640.42 v2(14292.41,7640.42) 14309.9,7657.91 C44.1@14309.9,7698 ; C47.1@14273.82,7779 14311.31,7779 v2(14331.79,7758.52) 14332.42,7758.52 C22.1@14351.9,7778 ; C46.1@14312.36,8173.46 C46.1@14311.82,8174 ; v2(14331.79,7522.32) 14350.99,7541.52 C62.1@14350.99,7578.8 ; v2(14331.79,8309.69) 14337.13,8309.69 14355.82,8291 C32.1@14391.9,8291 ; C309.1@14391.36,7702.46 14410.52,7683.3 v2(14410.52,7679.79) ; C45.1@14394.82,8015 14410.52,8030.7 v2(14410.52,8073.47) ; v2(14410.52,7601.05) 14427.11,7584.46 C310.1@14430.36,7584.46 ; v2(14410.52,8191.57) 14431.09,8171 C38.1@14468.9,8171 ; C11.1@14467.36,8057.46 14489.26,8035.56 v2(14489.26,8034.1) ; C59.1@14469.36,7702.46 14502.44,7702.46 C65.1@14509.36,7695.54 14509.36,7659.69 v2(14528.63,7640.42) ; v2(14489.26,7837.27) 14508.65,7856.67 C7.1@14508.65,7858.35 ; v2(14489.26,7955.37) 14491.91,7955.37 C12.1@14508.38,7938.91 ; v2(14528.63,7797.9) 14547.73,7817 C304.1@14547.73,7819.21 ; v2(14528.63,7876.62) 14547.82,7895.82 C293.1@14547.82,7898.25 ; v2(14528.63,7994.73) 14528.97,7994.73 C294.1@14546.62,7977.08 ; C10.1@14546.62,8058.93 14567.99,8037.57 v2(14567.99,8034.1) 14570.72,8034.1 C301.1@14587.36,8017.46 ; v2(14567.99,7955.37) 14569.45,7955.37 C299.1@14587.36,7937.46 ; v2(14567.99,8191.57) 14570.25,8191.57 C21.1@14588.36,8173.46 C20.1@14625.36,8136.46 ; C60.1@14587.91,7582.83 C61.1@14623.5,7618.43 ; C8.1@14627.36,7814.54 14630.1,7814.54 v2(14646.74,7797.9) ; C298.1@14627.36,7894.54 14645.28,7876.62 v2(14646.74,7876.62) ; C15.1@14627.36,7974.54 14646.74,7993.92 v2(14646.74,7994.73) ; C33.1@14631.82,8292 14668.4,8292 v2(14686.09,8309.69) ; C296.1@14666.9,7858.4 14686.09,7839.21 v2(14686.09,7837.27) ; C295.1@14667.36,7937.46 14668.18,7937.46 v2(14686.09,7955.37) ; C300.1@14667.36,8017.46 14684,8034.1 v2(14686.09,8034.1) 14703.9,8051.91 C307.1@14703.9,8054 ; C297.1@14707.36,7894.54 14725.28,7876.62 v2(14725.46,7876.62) ; C9.1@14707.36,7974.54 14725.46,7992.64 v2(14725.46,7994.73) ; C23.1@14743.02,8016.76 14747.49,8016.76 v2(14764.84,8034.1) ; C63.1@14747.36,7584.46 14787.61,7584.46 v2(14804.2,7601.05) ; v2(14764.84,7679.79) 14782.05,7697 C77.1@14821.9,7697 ; C35.1@14824.36,8129.54 14841.06,8112.84 v2(14882.94,8112.84) ; C72.1@14827.82,7936 14863.57,7936 v2(14882.94,7955.37) 14866.77,7971.54 C76.1@14862.36,7971.54 ; v2(14843.57,8309.69) 14860.9,8292.36 C39.1@14860.9,8289 ; C64.1@14902.36,7584.46 14918.95,7601.05 v2(14922.31,7601.05) ; C75.1@14944.82,8170 14979.47,8170 v2(15001.04,8191.57) ; C68.1@14979.36,7822.46 14986.23,7822.46 v2(15001.04,7837.27) 14982.36,7855.95 C69.1@14982.36,7890.54 ; C73.1@14981.36,8051.54 14983.6,8051.54 v2(15001.04,8034.1) ; v2(15001.04,7679.79) 15023.82,7657.01 C71.1@15023.82,7620 ; C74.1@15020.36,8333.46 15024.83,8333.46 v2(15040.44,8349.07) ; R53.2@15132.51,8201.22 15168.74,8164.99 C281.1@15169.58,8164.99 ; C287.1@15165.9,7946 15189.9,7922 15261.36,7922 15272.12,7932.77 v2(15272.12,7938.52) ; C279.1@15165.9,7986 15165.9,8020.54 15172.36,8027 15208.51,8027 C278.1@15210.25,8028.74 ; C281.1@15166.07,8165.83 15175.34,8156.56 R51.2@15175.34,8131.85 ; C278.1@15206.72,8026.95 15234.56,8026.95 v2(15240.63,8033.02) ; C288.1@15212.24,7847.09 15215.29,7844.03 v2(15240.63,7844.03) 15240.63,7819.6 15228.38,7807.35 15256.74,7779 v3(15286.36,7779) ; C285.1@15212.4,8334.26 15226.1,8347.97 v2(15240.63,8347.97) ; v3(15216.36,8450) 15263.36,8450 15383.36,8330 15383.36,8237.24 C104.2@15365.6,8219.48 ; v2(15272.12,8033.02) 15272.12,8035.19 15287.19,8050.26 15331.14,8050.26 C286.1@15349.12,8068.23 ; R186.2@15351.36,7945.96 15387.68,7909.64 R187.2@15409.36,7909.64 ; C283.1@15405.48,8027.17 15446.35,7986.31 15477.31,7986.31 15492.59,7971.03 v2(15492.59,7970.02) ; R187.2@15407.17,7910.48 15426.15,7910.48 v2(15461.09,7875.53) 15447.63,7875.53 15420.44,7848.34 15420.44,7815.46 C289.1@15422.9,7813 ; C282.1@15431.5,8119.59 15438.45,8112.64 15483.31,8112.64 15492.59,8121.92 v2(15492.59,8127.49) ; v2(15524.08,7875.53) 15531.48,7868.14 C290.1@15548.93,7868.14 ; v2(15524.08,7938.52) 15544.48,7958.93 C291.1@15552.51,7958.93 ; v2(15524.08,8033.02) 15550.05,8058.98 C292.1@15551.46,8058.98 ; v2(15524.08,8221.99) 15535.69,8210.38 C284.1@15553.25,8210.38
  Bottom Layer w6.2: v3@17347.36,9900 v3(17347.52,9900)
  Bottom Layer w7.9: v3(14645.36,8237) 14666.73,8215.63 C40.1@14666.73,8212.69
  Bottom Layer w10: v3(12683.16,5835) R121.2@12683.16,5870.63 ; R120.2@12685.19,6073.13 v3(12685.19,6112) ; R149.1@12722.43,7380.4 R149.1@12724.54,7380.4 ; R149.1@12723.13,7381.8 R149.1@12724.54,7380.4 ; v3(12745.14,8494.22) 12745.49,8494.57 D4.1@12745.49,8540.27 ; Q16.2@12750.31,7315.96 12750.31,7354.62 R149.1@12724.54,7380.4 ; v4@12775.62,7379.93 12775.15,7380.4 R149.1@12724.54,7380.4 ; v3(12874.49,8493.87) 12874.84,8494.22 D2.1@12874.84,8538.16 ; D1.1@13008.41,8538.51 13008.41,8494.57 v3(13008.76,8494.22) ; v4@13096.45,7513.18 13097.02,7513.75 R198.1@13097.02,7565.21 ; v3(13097.93,8197.53) R196.1@13097.93,8238.31 ; R197.1@13098.58,7891.73 13098.58,7851.19 v3(13098.81,7850.96) ; v3(13175.02,8494.22) 13175.02,8537.1 D3.1@13176.43,8538.51 ; C275.1@13630.9,7921 13630.9,7894.46 v3(13631.36,7894) ; C265.1@13630.9,7961 13631.36,7961.46 v3(13631.36,7989) ; v3(13639.28,8080) R1.2@13639.28,8106.34 ; C264.1@13968.97,8075.32 13979.04,8075.32 13988.36,8066 14004.36,8066 14020.36,8050 14042.91,8050 C103.2@14065.34,8027.56 ; v2(14213.67,8034.1) 14233.25,8014.52 C53.1@14233.25,7978.83 ; C49.1@14385.89,7932.42 14394.82,7941.35 C45.1@14394.82,8015 ; C311.1@14389.36,8175.46 14394.41,8175.46 v2(14410.52,8191.57) ; C50.1@14393.82,7857 14434.83,7815.99 C306.1@14469.28,7815.99 14489.26,7835.96 v2(14489.26,7837.27) ; C305.1@14467.36,7977.46 14489.26,7955.56 v2(14489.26,7955.37) ; v3(14487.36,8111) 14502.82,8111 C303.1@14509.36,8104.46 ; v2(14489.26,7522.32) 14489.92,7521.66 C55.1@14489.92,7426 ; v2(14489.26,8034.1) 14492.72,8034.1 C302.1@14508.36,8018.46 ; C41.1@14548.36,8137.46 14567.36,8118.46 v3(14567.36,8114) ; v2(14567.99,7837.27) 14587.36,7856.64 C14.1@14587.36,7857.46 ; C25.1@14586.36,7658.54 14546.75,7658.54 v2(14528.63,7640.42) 14548.31,7620.74 14621.2,7620.74 C61.1@14623.5,7618.43 ; v2(14646.74,7797.9) 14646.92,7797.9 C19.1@14668.82,7776 ; v2(14686.09,8309.69) 14686.09,8305.81 C34.1@14703.9,8288 ; C36.1@14706.36,8138.46 14759.47,8191.57 v2(14764.84,8191.57) ; C13.1@14707.36,7814.54 14708.82,7814.54 v2(14725.46,7797.9) 14726.92,7797.9 C16.1@14748.82,7776 ; C58.1@14707.82,7737 14707.82,7658.06 v2(14725.46,7640.42) ; C308.1@14746.91,7849.15 14752.96,7849.15 v2(14764.84,7837.27) ; v3(14762.36,6236) U122.1@14802.7,6236 ; C57.1@14783.36,7617.54 14787.71,7617.54 v2(14804.2,7601.05) ; C24.1@14785.36,8253.46 14785.36,8287 14789.36,8291 14822.36,8291 14824.36,8293 14826.88,8293 v2(14843.57,8309.69) ; C70.1@14820.9,7858 14841.63,7837.27 v2(14843.57,7837.27) ; v3@15012.36,6146 v3(15012.95,6146) ; C141.1@15117.82,6247 15152.82,6247 v5(15160.59,6239.23) ; C143.1@15118.82,6464 v3(15150.36,6464) ; C144.1@15207.36,6197.46 C132.2@15247.36,6197.46 15262.95,6213.05 v5(15262.95,6239.23) ; v5(15314.13,6239.23) 15327.36,6226 C142.1@15327.36,6197.46 C133.2@15367.36,6197.46 ; v3(15411.36,6189) 15411.36,6143 15413.36,6141 C191.1@15450.9,6141 ; v3@16653.36,5692 v3(16653.36,5692.34) ; v3(17262.3,9721.38) v3@17262.3,9721.82
  Bottom Layer w15: C339.2@16824.18,7875.57 v4(16824.18,7938.44) v4(16824.18,7958) ; C335.2@16922.41,8018.05 C336.1@16922.41,7978.05 v3(16957.36,7978.05)
  Bottom Layer w20: v3@13559.18,8152.87 R26.2@13594.16,8152.87 ; v3(13638.31,7834.21) 13638.64,7834.54 C274.1@13677.36,7834.54 ; v3(13646.66,8014.75) 13646.87,8014.54 C266.1@13677.36,8014.54 ; C273.1@13703.9,7790 13703.9,7765.68 v3(13704,7765.58) ; C106.2@13852.9,6402 C107.1@13852.9,6438 v1(13852.9,6479) ; v1(13971.36,6307) 13990.82,6307 C109.1@14011.36,6286.46 C108.2@14051.36,6286.46 ; C271.1@14022.36,7769.54 14078.34,7769.54 C3.1@14082.36,7773.56 ; v3(14040.36,7360) 14213.31,7360 C4.1@14214.71,7361.41 ; C55.1@14489.92,7426 14489.92,7358.18 C54.1@14522.1,7326 ; X1.2@14752.02,7194.53 14752.02,7166.33 14771.36,7147 14887.36,7147 14892.36,7152 14892.36,7335.85 C147.1@14892.21,7336 ; C149.1@14843.93,5546.58 14843.93,5496.87 v3(14845.47,5495.33) ; U102.1@14913.59,6345.2 15077.52,6345.2 v3(15078.01,6344.71) ; C184.2@14982.61,5866 15037.99,5921.38 C128.1@15037.99,5976 15075.9,6013.91 C135.2@15075.9,6046 C136.2@15075.9,6086 C145.1@15075.9,6126 C146.1@15075.9,6166 ; C290.1@15548.93,7868.14 v3(15581.36,7868.14) ; C292.1@15552.36,8057.46 v3(15597.36,8057.46) ; C291.1@15552.51,7958.93 v3(15581.36,7958.93) ; v3(15598.82,8086) C105.2@15598.82,8106 ; C343.1@16580.36,8399.46 v3(16580.36,8446) ; U114.2@16674.22,8442.55 16674.22,8491.4 C344.1@16676.82,8494 v1(16676.82,8525.85) 16676.82,8557.46 v1(16677.36,8558) ; C339.2@16824.18,7875.57 16824.18,7834.07 C340.1@16825.16,7833.09 ; C171.1@16992.36,9980.46 C162.2@17047.36,9980.46 ; C334.1@17051.58,8095.61 C333.2@17091.96,8095.61 ; C333.2@17092.97,8096.63 C333.2@17091.96,8095.61 ; v1(17140.36,8095.61) C333.2@17091.96,8095.61 ; C330.1@17297.36,7799.54 17337.66,7799.54 C319.2@17338.04,7799.15 17356.97,7799.15 C322.2@17407.36,7748.76 ; C331.2@17328.04,7704.15 C332.1@17328.04,7744.15
  Bottom Layer w30: C42.1@14002.36,7635.74 14044.54,7593.56 C43.1@14102.36,7593.56 ; C17.1@14172.62,8576 14199.8,8548.82 C29.1@14199.8,8471 C18.1@14199.8,8411 ; C31.1@14639.92,8406 14639.92,8483.82 C30.1@14672.1,8516 ; C5.1@14897.62,8521 14959.8,8458.82 C6.1@14959.8,8411 ; C67.1@15107.36,7653.56 15180.18,7653.56 C66.1@15207.36,7680.74
  Bottom Layer w40: C66.1@15207.36,7680.74 v4(15254.13,7727.52) 15270.36,7743.74 v3(15270.36,7745)
  Bottom Layer w50: C183.2@15607.11,6046 v1(15661.64,6046) v1(15690.36,6046)
  other v1: 14253.71,5055.13 14357.94,5055.59 14457.31,5055.53 14561.54,5055.99 14656.87,5056.07 14860.47,5056.47 15895.95,5055.71 16000.18,5056.17 16099.55,5056.11 14761.11,5056.54 14964.71,5056.94 15072.42,5057.44 16203.78,5056.57 16299.12,5056.65 16403.35,5057.11 16502.72,5057.05 15176.65,5057.91 15276.02,5057.84 15380.25,5058.31 15475.58,5058.39 16606.95,5057.52 16714.66,5058.02 16818.89,5058.49 16918.26,5058.42 15579.82,5058.85 15679.18,5058.79 15783.42,5059.25 17022.49,5058.89 17117.83,5058.96 17222.06,5059.43 17321.43,5059.37 17523.35,5059.44 17622.72,5059.38 17425.66,5059.83 17726.95,5059.84 17822.28,5059.92 17926.52,5060.38 18025.88,5060.32 18130.12,5060.78 12635.11,5064.46 12739.34,5064.93 12838.71,5064.86 12942.94,5065.33 13038.28,5065.4 13142.51,5065.87 13241.88,5065.81 13346.11,5066.27 13453.82,5066.78 13558.06,5067.24 13657.42,5067.18 13761.66,5067.64 13856.99,5067.72 13961.22,5068.18 14060.59,5068.12 14164.82,5068.59 18337.03,5253.56 12513.04,5262.64 18336.56,5357.79 12512.57,5366.88 18336.48,5453.12 12512.5,5462.21 18336.02,5557.36 12512.03,5566.44 18336.08,5656.72 12512.1,5665.81 18335.62,5760.96 12511.63,5770.04 14916.36,5839 18337.48,5860.59 12513.49,5869.67 14916.36,5871 14916.36,5902 18337.4,5955.92 12513.41,5965.01 18336.93,6060.16 12512.95,6069.24 18337,6159.52 12513.01,6168.61 13367.29,6196.79 13330.04,6198.16 13972.36,6248 14120.36,6248 13331.18,6248.61 13367.4,6248.61 18336.53,6263.76 12512.55,6272.84 14121.36,6303 13971.04,6360 14067.36,6360 14016.36,6361 14121.36,6361 18336.92,6361.45 12512.94,6370.53 14120.59,6410.31 14068.36,6411 18336.99,6460.81 12513,6469.9 18336.52,6565.05 12512.54,6574.13 12984.36,6617 13022.69,6617.5 13059.36,6617 12984.97,6660.1 13022.69,6660.1 13057.17,6660.1 18336.45,6660.38 12512.46,6669.46 14649.36,6686 13369.09,6691.25 13331.84,6692.62 12984.36,6710 13022.69,6710.81 13057.36,6712 14649.36,6717 13332.98,6743.07 13369.2,6743.07 18335.98,6764.61 12511.99,6773.7 18336.04,6863.98 12512.06,6873.06 18335.58,6968.21 12511.59,6977.3 18342.65,7078.99 12518.66,7088.08 13807.36,7165 13857.36,7165 18342.57,7174.33 12518.58,7183.41 13806.36,7209 13855.36,7210 15201.36,7223 15167.36,7254 15202.36,7254 18342.1,7278.56 12518.12,7287.64 18342.17,7377.93 12518.18,7387.01 18341.7,7482.16 12517.72,7491.24 18342.09,7579.85 12518.11,7588.93 13781.36,7642 13813.36,7643 13780.36,7677 13813.36,7678 18342.16,7679.22 12518.17,7688.3 17377.32,7696.75 17422.71,7696.52 18341.69,7783.45 17003.36,7789 17055.28,7789.22 17109.8,7789.95 12517.71,7792.53 17003.52,7849.27 17054.92,7848.52 17110.54,7848.89 18341.62,7878.78 12517.63,7887.87 17109.06,7908.56 18341.15,7983.02 12517.16,7992.1 18341.21,8082.38 12517.23,8091.47 18340.75,8186.62 12516.76,8195.7 16009.36,8228 16009.36,8271 16063.36,8271 18340.33,8302.15 12516.35,8311.23 16008.36,8311 16063.36,8311 16115.36,8312 18340.26,8397.48 12516.27,8406.57 15929.36,8420 15966.36,8420 18339.79,8501.72 12515.81,8510.8 17327.1,8553.84 17389.11,8554.58 16895.98,8556.83 16839.94,8557.57 18339.86,8601.08 12515.87,8610.17 15938.36,8646 13860.36,8677 13939.36,8677 13459.36,8678 13536.36,8678 13695.56,8677.91 13776.36,8678 13641.36,8680 15474.36,8688 15553.36,8688 15632.36,8688 15153.36,8689 15234.36,8689 15313.36,8689 15392.36,8689 18339.39,8705.32 12515.4,8714.4 13963.7,8803.23 14032.21,8803.23 18339.78,8803.01 13524.6,8803.94 13455.79,8804.55 12515.8,8812.09 13379.36,8834.39 13413.16,8834.08 14093.87,8833.83 14094.33,8878.13 13378.45,8881.28 13411.64,8880.97 18339.85,8902.37 12515.86,8911.46 18339.38,9006.61 12515.39,9015.69 17495.56,9073.75 17462.02,9075.07 18339.3,9101.94 12515.32,9111.02 17495.9,9118.58 17462.36,9120.9 17461.69,9163.07 17496.23,9163.07 18338.84,9206.17 12514.85,9215.26 18338.9,9305.54 12514.92,9314.62 18338.44,9409.77 12514.45,9418.86 17672.46,9455.07 17703.84,9478.98 17671.96,9501.89 18340.33,9534.55 12516.35,9543.64 18340.26,9629.89 12516.27,9638.97 15537.86,9645.07 15484.87,9646.55 14572.4,9691.91 14612.11,9692.97 15538.84,9694.38 15485.36,9696.35 13776.29,9701.71 13812.63,9702.68 12947.12,9706.32 12984.82,9706.32 18339.79,9734.12 14572.4,9738.31 14612.47,9737.96 13812.54,9739.16 13777.13,9739.6 15538.35,9740.5 15485.36,9742.47 12515.81,9743.21 12948.16,9743.37 12985.72,9743.75 15538.84,9788.59 18339.86,9833.49 17574.24,9840.73 17618.96,9840.95 17660.58,9841.17 12515.87,9842.57 15096.04,9848.94 15059.48,9849.65 15591.83,9875.43 15548.16,9875.92 15059.13,9887.61 15095.69,9888.31 15547.18,9906.35 15591.34,9905.85 17350.34,9932.58 14622.48,9934.09 17381.55,9933.91 14652.71,9934.8 18339.39,9937.72 12928.01,9941.42 12890.99,9942.3 12515.4,9946.81 13753.47,9946.85 13716.46,9947.72 14622.13,9962.57 14653.06,9962.92 12890.12,9969.7 12928.01,9970.57 17349.89,9973.98 17380.44,9973.98 13715.58,9975.12 13753.47,9975.99 16937.13,9981.72 16964.73,9981.86 17349.01,10019.14 17380,10019.8 18339.78,10035.41 12515.8,10044.49 13057.78,10067.04 13104.88,10067.04 13150.58,10067.04 13793.41,10086.17 13701.67,10088.28 13748.77,10087.93 13058.49,10115.9 13104.53,10116.25 13150.93,10116.96 18339.85,10134.78 13701.67,10136.09 13748.77,10136.09 13794.47,10136.09 12515.86,10143.86 17589.05,10161.43 17446.59,10162.43 17518.32,10161.93 13702.37,10184.95 13748.42,10185.3 13794.82,10186 17446.1,10209.25 18105.89,10226.77 18048.11,10228.09 18339.38,10239.01 12515.39,10248.09 17445.1,10254.08 18046.78,10270.6 18104.23,10270.93 18339.3,10334.34 12515.32,10343.43 16134.13,10414.3 16219.47,10413.64 16286.55,10413.97 16032.84,10414.97 18338.84,10438.58 12514.85,10447.66 16284.89,10452.49 16133.46,10453.16 16218.14,10452.82 16033.18,10453.82 16217.15,10497.99 16284.22,10497.65 16217.59,10537.06 16284.22,10537.39 18338.9,10537.94 12514.92,10547.03 12530.36,10639.35 18338.44,10642.18 12514.45,10651.26 16714.14,10682.79 12529.33,10736.97 12588.94,10846.93 14311.44,10878.13 14415.67,10878.6 14515.04,10878.53 14619.27,10879 14714.61,10879.08 14918.21,10879.48 15953.68,10878.71 16057.92,10879.18 16157.28,10879.11 14818.84,10879.54 15022.44,10879.94 15130.15,10880.45 16261.52,10879.58 16356.85,10879.65 16461.08,10880.12 16560.45,10880.06 15234.38,10880.91 15333.75,10880.85 15437.98,10881.31 15533.32,10881.39 16664.68,10880.52 16772.39,10881.03 16876.63,10881.49 16975.99,10881.43 15637.55,10881.86 15736.92,10881.79 15841.15,10882.26 17080.23,10881.89 17175.56,10881.97 17279.79,10882.43 17379.16,10882.37 17581.08,10882.44 17680.45,10882.38 17483.39,10882.84 17784.68,10882.85 17880.02,10882.92 17984.25,10883.39 18083.62,10883.32 18187.85,10883.79 12692.84,10887.47 12797.08,10887.93 12896.44,10887.87 13000.68,10888.33 13096.01,10888.41 13200.24,10888.87 13299.61,10888.81 13403.84,10889.28 13511.55,10889.78 13615.79,10890.25 13715.15,10890.18 13819.39,10890.65 13914.72,10890.72 14018.96,10891.19 14118.32,10891.13 14222.56,10891.59
  other v3: 12991.11,5718.45 12942.59,5719.36 12892.47,5720.05 12892.47,5754.21 12990.88,5753.99 12942.59,5754.9 12990.42,5787.93 12853.52,5789.07 12941.68,5788.84 12892.7,5789.75 12914.34,5825.74 18011.39,6907.06 17987.26,7188.44 13559.12,8152.93
  other v4: 18225.73,5158.3 18042.12,5161.42 12811.15,5190.32 12634.4,5191.69 18046.23,5313.51 18223.29,5317.55 12632.34,5344.47 12804.99,5347.9 14377.61,5846.25 14377.19,5867.71 12754.3,7380.16 12775.15,7379.93 13097.16,7513.65 13960.99,9598.02 16611.03,9663.29 18042.74,10626.52 12807.08,10630.09 18225.66,10629.95 12625.19,10636.26 12633.41,10770.62 12816.33,10774.99 18055.76,10782.73 18220.87,10787.52
  other v5: 15211.77,6239.23 15160.59,6290.41 15314.13,6290.41 15160.59,6341.59 15262.95,6341.59 15314.13,6341.59 15211.77,6392.77 15262.95,6392.77
  other v6: 17130.99,9507.63 17170.36,9507.63 17209.73,9507.63 17130.99,9547 17170.36,9547 17211.07,9547 17130.99,9586.37 17170.36,9586.37 17208.93,9586.37
  other v7: 16092.35,8486.48 16078.57,8516
HDMI_SCL: pad.TP1 Q12.2 R109.1 U8.A13 U33.6 | length 2909.4
  Top Layer w4.7: U8.A13@14666.41,8329.4 14666.75,8329.4 v3(14686.36,8349) ; U33.6@16378.86,9811 pad.TP1@16466.71,9811 16526.36,9811 v3(16569.36,9854) 16569.36,9888.5 R109.1@16569.23,9888.62 16569.23,9943.89 Q12.2@16574.59,9949.25
  L3_SIG1 w5: v3(14686.36,8349) 16020.36,9683 16516.36,9683 16569.36,9736 v3(16569.36,9854)
HDMI_SDA: pad.TP2 Q11.2 R108.1 U8.A17 U33.5 | length 3228.9
  Top Layer w4.7: U33.5@16378.86,9761 pad.TP2@16468.53,9761 16670.36,9761 v3(16763.36,9854) 16763.36,9902.75 R108.1@16764.23,9903.62 16764.23,9962.79 Q11.2@16767.38,9965.94
  Top Layer w10: U8.A17@14823.89,8329.4 v2(14843.57,8349.07)
  L3_SIG1 w5: v2(14843.57,8349.07) 14843.57,8442.21 16025.36,9624 16647.36,9624 16763.36,9740 v3(16763.36,9854)
HP1_L: CN8.1 U124.6 U124.7 | length 1378.2
  Top Layer w10: U124.7@16892.36,6925.02 16892.36,6985 v4(16902.36,6995) 16928.36,6995 16942.36,6981 U124.6@16942.36,6925.02 ; v3(17767.36,6646) 17799.36,6614 17799.36,6489.8 CN8.1@17810.55,6478.61
  L6_SIG2 w10: v4(16902.36,6995) 17260.36,6637 17758.36,6637 v3(17767.36,6646)
HP1_R: CN8.2 U106.6 U106.7 | length 1581.8
  Top Layer w10: U106.7@16892.36,6396.02 16892.36,6434 v4(16912.36,6454) 16924.36,6454 16942.36,6436 U106.6@16942.36,6396.02 ; CN8.2@18129.45,6242.39 18129.45,6157.91 v3(18134.36,6153)
  L3_SIG1 w10: v4(16912.36,6454) 17057.36,6454 17358.36,6153 v3(18134.36,6153)
HP2_L: CN9.1 U124.13 U124.14 | length 1101
  Top Layer w10: U124.13@17142.36,6706.98 17142.36,6664 17157.36,6649 v4(17176.36,6649) 17192.36,6665 U124.14@17192.36,6706.98 ; v3(17775.36,6188) 17810.55,6152.81 CN9.1@17810.55,6039.29
  L3_SIG1 w10: v4(17176.36,6649) 17637.36,6188 v3(17775.36,6188)
HP2_R: CN9.2 U106.13 U106.14 | length 1424.4
  Top Layer w10: U106.13@17142.36,6177.98 17142.36,6136 17165.36,6113 v4(17173.36,6113) 17192.36,6132 U106.14@17192.36,6177.98 ; CN9.2@18129.45,5803.07 18129.45,5707.91 v3(18130.36,5707)
  L3_SIG1 w10: v4(17173.36,6113) 17173.36,6032 17498.36,5707 v3(18130.36,5707)
  other v3: 18130.36,5707
HP_L: CN7.1 R193.1 U124.3 | length 1149.9
  Top Layer w10: U124.3@17092.36,6925.02 v3(17092.36,6991) ; v3(17810.36,7268) 17810.14,7267.78 R193.1@17810.14,7185 17810.55,7184.59 CN7.1@17810.55,7039.88
  L6_SIG2 w10: v3(17092.36,6991) 17092.36,7030 17330.36,7268 v3(17810.36,7268)
HP_R: CN7.2 R194.2 U106.3 | length 1414.9
  Top Layer w10: U106.3@17092.36,6396.02 v3(17092.36,6461) ; CN7.2@18129.45,6803.66 18131.58,6801.53 R194.2@18131.58,6677 v3(18131.58,6603)
  L6_SIG2 w10: v3(17092.36,6461) 17092.36,6547 17148.36,6603 v3(18131.58,6603)
HSYC: D6.4 DSUB1.13 Q3.3 R94.2 | length 1099.3
  Top Layer w4.7: Q3.3@13737.05,5856.67 13737.05,5756.27 R94.2@13753.32,5740 ; R94.2@13750.21,5743.96 13767.36,5726.81 13767.36,5525.68 13772.06,5520.98 13809.91,5520.98 v3(13810.13,5521.2)
  L6_SIG2 w5: v3(13810.13,5521.2) 13810.13,5490.77 13774.36,5455 13774.36,5334 13720.36,5280 13720.36,5163 13759.36,5124 13968.36,5124 13976.36,5132 13976.36,5165.5 DSUB1.13@13977.33,5166.47
IN_5V: D21.1 F1.2 USB3.18 | length 623.2
  Top Layer w20: F1.2@16590.33,10496 16597.36,10503.03 16598.39,10502 16797.36,10502 16875.36,10424 16875.36,10277 16890.36,10262 16940.36,10262 16972.04,10293.68 USB3.18@16972.04,10333.17
IN_HPD: D16.4 Q10.3 R112.1 USB3.19 | length 787.1
  Top Layer w4.7: Q10.3@16353.26,10221.73 16354.4,10222.87 R112.1@16354.4,10281 16355.4,10280 v3(16386.36,10280) ; v3(16624.96,10232) D16.4@16624.96,10270.88 16625.36,10271.28 v3(16625.36,10304)
  Bottom Layer w4.7: v3(16386.36,10280) 16434.36,10232 v3(16624.96,10232) ; v3(16625.36,10304) 16697.36,10376 16867.09,10376 USB3.19@16932.67,10310.42
IN_SCL: D16.1 Q12.3 R111.1 USB3.15 | length 789.8
  Top Layer w4.7: Q12.3@16537.19,10027.99 16537.19,10039.17 16501.36,10075 16501.36,10135 16518.4,10152.04 16540.36,10152.04 16537.36,10155.04 16537.36,10268 16601.36,10332 16674.36,10332 16699.76,10357.4 D16.1@16699.76,10381.12 16699.76,10420.6 v3(16699.36,10421)
  Bottom Layer w4.7: v3(16699.36,10421) 16719,10401.35 USB3.15@16932.67,10401.35
IN_SDA: D16.6 Q11.3 R110.2 USB3.16 | length 789.1
  Top Layer w4.7: v3(16700.36,10315) 16700.36,10271.48 D16.6@16699.76,10270.88 16727.19,10243.45 R110.2@16727.19,10155.66 16752.69,10155.66 16768.36,10140 16768.36,10092 16729.98,10053.62 Q11.3@16729.98,10044.68
  Bottom Layer w4.7: v3(16700.36,10315) 16736.36,10351 16855.36,10351 16921.36,10285 16969.36,10285 17013.36,10329 17013.36,10368 17001.36,10380 16973.36,10380 USB3.16@16972.04,10378.68
ISEL: RN2.7 SW1.2 U3.13 | length 511.2
  Top Layer w4.7: RN2.7@14724.61,5944.44 14724.61,5970.75 14714.36,5981 SW1.2@14714.36,6019 14714.36,6100 14740.36,6126 14841.36,6126 14942.78,6227.42 U3.13@15012.95,6227.42
MIC: CN7.4 R191.2 R192.2 | length 154.3
  Top Layer w10: CN7.4@17853.86,6803.66 17853.86,6651.54 R192.2@17855.4,6650
MIC1: CN8.4 U124.10 | length 1411
  Top Layer w10: U124.10@16992.36,6706.98 16993.36,6707.98 v3(16993.36,6777) ; CN8.4@17853.86,6242.39 v4(17853.86,6330)
  L3_SIG1 w10: v3(16992.36,6777) 17757.36,6777 17853.86,6680.5 v4(17853.86,6330)
  Bottom Layer w10: v3(16992.36,6777) v3(16993.36,6777)
MIC1_OR: R191.1 U124.8 U124.9 | length 1080.9
  Top Layer w10: U124.8@16892.36,6706.98 16892.36,6665 v4(16911.36,6646) 16921.36,6646 16942.36,6667 U124.9@16942.36,6706.98 ; v3(17771.36,6695) 17816.32,6695 R191.1@17821.32,6690
  L3_SIG1 w10: v4(16911.36,6646) 16960.36,6695 v3(17771.36,6695)
MIC2: CN9.4 U106.10 | length 1179.5
  Top Layer w10: U106.10@16992.36,6177.98 v3(16992.36,6250) ; CN9.4@17853.86,5803.07 v3(17853.86,5907)
  L3_SIG1 w10: v3(16992.36,6250) 17143.36,6250 17373.36,6020 17740.86,6020 v3(17853.86,5907)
